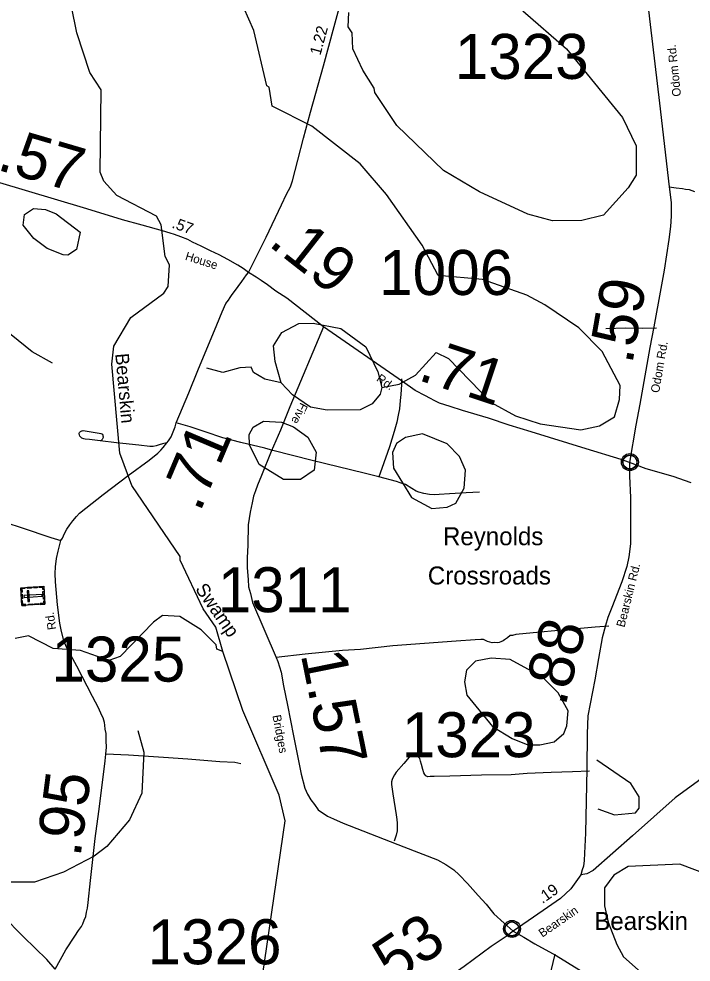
# Model space of a CAD drawing. Extents: x 2093524 to 2270757, y 289120 to 570408.
# Drawn here: x 2162986 to 2170455, y 474784 to 485262 of the extents above; entities that cross this region are included whole.
import ezdxf

# ---------------------------------------------------------------- set-up
doc = ezdxf.new("R2010")
doc.units = 0
for name, color, linetype in [('Exist Civil Demographics Community CELL', 7, 'Continuous'), ('Exist Civil Demographics Community Label', 7, 'Continuous'), ('Exist Cultural Cemetery CELL', 7, 'Continuous'), ('Exist Hydrographic Creek Single Shore', 7, 'Continuous'), ('Exist Hydrographic Misc Water Feature', 7, 'Continuous'), ('Exist Hydrographic Pond Under 1500 Sq Ft', 7, 'Continuous'), ('Exist Hydrographic Swamp Label', 7, 'Continuous'), ('Exist Road Non-System Type 51', 7, 'Continuous'), ('Exist Road Secondary Mileage Hundredths English Label', 7, 'Continuous'), ('Exist Road Secondary Type 51 Attributed', 7, 'Continuous'), ('Exist Road Secondary Type 51 Label', 7, 'Continuous'), ('Exist Road Secondary Type 51 Number Label', 7, 'Continuous')]:
    doc.layers.add(name, color=color, linetype=linetype)

msp = doc.modelspace()

# ---------------------------------------------------------------- linework, layer by layer
at = {"layer": 'Exist Civil Demographics Community CELL'}
for points in [[(2169697, 480351), (2169698, 480356), (2169700, 480363), (2169703, 480370), (2169706, 480376), (2169709, 480382), (2169713, 480387), (2169717, 480391), (2169722, 480396), (2169727, 480400), (2169733, 480404), (2169738, 480407), (2169743, 480409), (2169748, 480412), (2169754, 480413), (2169758, 480414), (2169763, 480415), (2169767, 480416), (2169773, 480416), (2169778, 480416), (2169783, 480416), (2169788, 480415), (2169793, 480414), (2169798, 480413), (2169803, 480411), (2169810, 480408), (2169816, 480404), (2169821, 480401), (2169827, 480397), (2169830, 480394), (2169834, 480389), (2169838, 480385), (2169841, 480380), (2169844, 480375), (2169847, 480370), (2169849, 480365), (2169850, 480360), (2169851, 480355), (2169852, 480349), (2169853, 480344), (2169853, 480338), (2169853, 480333), (2169853, 480327), (2169852, 480322), (2169850, 480315), (2169848, 480310), (2169846, 480304), (2169843, 480298), (2169839, 480293), (2169836, 480288), (2169832, 480284), (2169826, 480279), (2169821, 480275), (2169816, 480271), (2169812, 480269), (2169805, 480265), (2169798, 480263), (2169792, 480261), (2169786, 480260), (2169781, 480259), (2169777, 480259), (2169771, 480259), (2169767, 480260), (2169761, 480260), (2169755, 480262), (2169751, 480263), (2169745, 480265), (2169741, 480267), (2169737, 480269), (2169730, 480273), (2169725, 480277), (2169720, 480282), (2169715, 480287), (2169712, 480291), (2169709, 480295), (2169705, 480302), (2169703, 480306), (2169702, 480310), (2169699, 480318), (2169697, 480325), (2169697, 480330), (2169696, 480336), (2169696, 480341), (2169697, 480347)], [(2168387, 475165), (2168388, 475171), (2168390, 475177), (2168393, 475185), (2168396, 475190), (2168399, 475196), (2168403, 475201), (2168407, 475206), (2168411, 475210), (2168417, 475215), (2168422, 475218), (2168427, 475221), (2168432, 475224), (2168438, 475226), (2168443, 475228), (2168448, 475229), (2168452, 475230), (2168457, 475230), (2168463, 475231), (2168467, 475231), (2168473, 475230), (2168478, 475230), (2168483, 475229), (2168488, 475227), (2168493, 475225), (2168500, 475222), (2168506, 475219), (2168511, 475215), (2168516, 475211), (2168519, 475208), (2168524, 475204), (2168527, 475199), (2168531, 475195), (2168534, 475190), (2168536, 475184), (2168538, 475179), (2168540, 475174), (2168541, 475170), (2168542, 475164), (2168543, 475159), (2168543, 475153), (2168543, 475147), (2168542, 475142), (2168541, 475136), (2168540, 475130), (2168538, 475124), (2168535, 475119), (2168532, 475113), (2168529, 475108), (2168526, 475103), (2168521, 475098), (2168516, 475093), (2168511, 475089), (2168506, 475086), (2168502, 475083), (2168495, 475080), (2168488, 475077), (2168482, 475076), (2168475, 475074), (2168471, 475074), (2168466, 475074), (2168461, 475074), (2168456, 475074), (2168451, 475075), (2168445, 475076), (2168440, 475077), (2168435, 475079), (2168431, 475081), (2168427, 475084), (2168420, 475088), (2168414, 475092), (2168409, 475096), (2168405, 475101), (2168402, 475105), (2168399, 475109), (2168395, 475117), (2168393, 475120), (2168391, 475124), (2168389, 475132), (2168387, 475139), (2168386, 475144), (2168386, 475151), (2168386, 475156), (2168386, 475162)]]:
    msp.add_lwpolyline(points, close=True, dxfattribs=at)
for centre, radius in [((2169775, 480338), 94.3), ((2169775, 480339), 76.7), ((2168465, 475153), 94.3), ((2168464, 475153), 76.7)]:
    msp.add_circle(centre, radius, dxfattribs=at)
at = {"layer": 'Exist Cultural Cemetery CELL'}
for points in [[(2163020, 478744), (2163008, 478943), (2163263, 478959), (2163275, 478760)], [(2163052, 478946), (2163052, 478935), (2163020, 478933), (2163023, 478892), (2163012, 478891), (2163008, 478943)], [(2163016, 478818), (2163013, 478870), (2163024, 478871), (2163027, 478819)], [(2163043, 478855), (2163044, 478836), (2163247, 478849), (2163245, 478867)], [(2163086, 478789), (2163104, 478790), (2163097, 478908), (2163079, 478907)], [(2163125, 478939), (2163082, 478936), (2163081, 478948), (2163125, 478950)], [(2163191, 478943), (2163148, 478940), (2163147, 478952), (2163190, 478954)], [(2163265, 478925), (2163253, 478925), (2163252, 478947), (2163211, 478944), (2163211, 478955), (2163263, 478959)], [(2163260, 478816), (2163254, 478901), (2163266, 478902), (2163271, 478817)], [(2163064, 478747), (2163063, 478758), (2163031, 478756), (2163028, 478797), (2163017, 478796), (2163020, 478744)], [(2163138, 478752), (2163094, 478749), (2163094, 478760), (2163137, 478763)], [(2163205, 478756), (2163161, 478753), (2163161, 478764), (2163204, 478767)], [(2163272, 478793), (2163261, 478792), (2163262, 478770), (2163222, 478768), (2163223, 478757), (2163274, 478760)]]:
    msp.add_lwpolyline(points, close=True, dxfattribs=at)
at = {"layer": 'Exist Hydrographic Creek Single Shore'}
for points in [[(2165253, 478235), (2165176, 478503), (2165033, 478709), (2164780, 479249), (2164780, 479291), (2164243, 480079), (2164107, 480436), (2164018, 481426), (2164042, 481628), (2164231, 481946), (2164596, 482214), (2164646, 482289), (2164661, 482531), (2164610, 482621), (2164568, 482973), (2164516, 483072), (2164074, 483301), (2163931, 483458), (2163889, 483560), (2163900, 484475), (2163774, 484665), (2163630, 485107), (2163450, 486006)], [(2164014, 467432), (2164010, 468065), (2164247, 468999), (2164236, 469491), (2164251, 469658), (2164366, 470059), (2164381, 470367), (2164454, 470717), (2164552, 470951), (2165138, 471903), (2165149, 472616), (2165237, 472845), (2165619, 474121), (2165945, 476355), (2165878, 476638), (2165473, 477578), (2165253, 478235)]]:
    msp.add_lwpolyline(points, dxfattribs=at)
at = {"layer": 'Exist Hydrographic Misc Water Feature'}
for points in [[(2167019, 481169), (2167210, 481204), (2167393, 481305), (2167624, 481557), (2167758, 481488), (2168235, 481000), (2168502, 480853), (2168778, 480763), (2169229, 480698), (2169436, 480740), (2169603, 480841), (2169660, 481034), (2169668, 481191), (2169466, 481566), (2169206, 481830), (2168830, 482087), (2168629, 482193), (2168136, 482366), (2167645, 482412), (2167468, 482747), (2167072, 483310), (2166779, 483650), (2166243, 484071), (2165802, 484293), (2165766, 484503), (2165741, 484520), (2165596, 485133), (2165486, 485385)], [(2163360, 481439), (2163134, 481565), (2162741, 481878)], [(2165902, 481220), (2165718, 481260), (2165593, 481335), (2165568, 481394), (2165442, 481384), (2165252, 481335), (2165076, 481381)], [(2165253, 478235), (2165186, 478260), (2165177, 478309), (2165010, 478476), (2164775, 478625), (2164584, 478633), (2164483, 478562), (2164111, 478180), (2163986, 478136), (2163670, 478244), (2163369, 478267), (2163093, 478407), (2162944, 478380)], [(2164308, 477356), (2164376, 477115), (2164352, 476662), (2164214, 476364), (2163964, 476070), (2163824, 475961), (2163484, 475784), (2163159, 475673), (2162718, 475672), (2162159, 475811), (2161691, 475981), (2161097, 476328), (2160529, 476710), (2160136, 477006), (2159691, 477471), (2159422, 477903), (2159305, 478036), (2159029, 478183), (2158887, 478199)], [(2169419, 476485), (2169603, 476419), (2169836, 476444), (2169877, 476496), (2169877, 476621), (2169784, 476770), (2169408, 477027)]]:
    msp.add_lwpolyline(points, dxfattribs=at)
at = {"layer": 'Exist Hydrographic Pond Under 1500 Sq Ft'}
for points in [[(2168915, 483020), (2168640, 483094), (2168105, 483341), (2167705, 483579), (2167185, 484078), (2166941, 484444), (2166933, 484493), (2166808, 484693), (2166697, 484931), (2166689, 485108), (2166646, 485175), (2166654, 485332)], [(2168586, 485352), (2169071, 484929), (2169693, 484166), (2169844, 483851), (2169846, 483526), (2169755, 483384), (2169482, 483081), (2169240, 483023), (2168915, 483020)], [(2163478, 482640), (2163302, 482713), (2163152, 482821), (2163034, 482971), (2163050, 483088), (2163150, 483155), (2163283, 483146), (2163400, 483098), (2163668, 482892), (2163627, 482700), (2163529, 482639), (2163478, 482640)], [(2165902, 481220), (2165834, 481455), (2165816, 481629), (2165907, 481778), (2166098, 481879), (2166257, 481883), (2166565, 481824), (2166841, 481618), (2166975, 481343), (2167019, 481169)], [(2167019, 481169), (2167001, 481094), (2166911, 480984), (2166779, 480918), (2166412, 480915), (2166228, 480948), (2166027, 481087), (2165902, 481220)], [(2165925, 480147), (2165657, 480310), (2165547, 480529), (2165546, 480644), (2165588, 480728), (2165705, 480795), (2165904, 480781), (2166038, 480729), (2166196, 480614), (2166290, 480448), (2166266, 480249), (2166116, 480147), (2165925, 480147)], [(2167576, 479822), (2167743, 479839), (2167842, 479883), (2167933, 480048), (2167949, 480248), (2167881, 480400), (2167746, 480541), (2167471, 480654), (2167280, 480612), (2167180, 480545), (2167139, 480444), (2167149, 480270), (2167350, 479945), (2167576, 479822)], [(2168774, 477197), (2168932, 477230), (2169040, 477323), (2169073, 477408), (2169088, 477575), (2168979, 477774), (2168803, 477948), (2168444, 478145), (2168235, 478159), (2168061, 478127), (2167961, 478027), (2167937, 477899), (2167963, 477751), (2168248, 477401), (2168465, 477269), (2168641, 477196), (2168774, 477197)], [(2171041, 473993), (2171274, 474021), (2171523, 474154), (2171697, 474396), (2171713, 474524), (2171661, 474807), (2171543, 475062), (2171133, 475477), (2170798, 475694), (2170331, 475873), (2169756, 475846), (2169598, 475750), (2169491, 475608), (2169492, 475411), (2169535, 475227), (2169628, 474979), (2169703, 474843), (2170197, 474407), (2170507, 474217), (2171041, 473993)]]:
    msp.add_lwpolyline(points, dxfattribs=at)
at = {"layer": 'Exist Road Non-System Type 51'}
for points in [[(2170072, 481825), (2169920, 481823), (2169726, 481825), (2169508, 481818)], [(2167238, 481262), (2167236, 481200), (2167231, 481089), (2167224, 481021), (2167216, 480932), (2167202, 480859), (2167187, 480781), (2167157, 480679), (2167103, 480509), (2167020, 480267), (2166984, 480175)], [(2165807, 480468), (2165719, 480493), (2165451, 480556), (2165253, 480609), (2165056, 480674), (2164888, 480730), (2164734, 480773)], [(2163889, 480573), (2163829, 480581), (2163773, 480588), (2163723, 480594), (2163707, 480596), (2163697, 480600), (2163687, 480604), (2163675, 480614), (2163665, 480628), (2163659, 480640), (2163657, 480650), (2163657, 480660), (2163661, 480668), (2163663, 480672), (2163671, 480678), (2163685, 480684), (2163691, 480686), (2163701, 480688), (2163789, 480674), (2163879, 480661), (2163897, 480657), (2163909, 480651), (2163915, 480647), (2163921, 480639), (2163921, 480629), (2163923, 480621), (2163923, 480613), (2163921, 480605), (2163917, 480597), (2163911, 480589), (2163899, 480579), (2163889, 480573)], [(2164631, 480553), (2164583, 480541), (2164545, 480529), (2164513, 480518), (2164477, 480512), (2164441, 480512), (2164321, 480528), (2164070, 480552), (2163889, 480573)], [(2166984, 480175), (2166838, 480210), (2166670, 480251), (2166532, 480286), (2166244, 480358), (2165807, 480468)], [(2168105, 480005), (2167955, 479998), (2167771, 479987), (2167657, 479978), (2167605, 479974), (2167547, 479978), (2167487, 479991), (2167429, 480005), (2167401, 480017), (2167351, 480045), (2167283, 480088), (2167223, 480108), (2167181, 480122), (2166984, 480175)], [(2169539, 478515), (2169387, 478505), (2169021, 478471), (2168700, 478441), (2168506, 478422), (2168470, 478412), (2168444, 478411), (2168416, 478385), (2168382, 478365), (2168366, 478353), (2168342, 478343), (2168324, 478335), (2168304, 478331), (2168272, 478333), (2168246, 478330), (2168194, 478346), (2168172, 478356), (2168148, 478366), (2168120, 478367), (2168054, 478365), (2167844, 478350), (2167141, 478296), (2166783, 478258), (2166582, 478245), (2166166, 478205), (2165846, 478168)], [(2165453, 476987), (2165385, 477001), (2165219, 477008), (2164863, 477040), (2164593, 477058), (2164205, 477084), (2163953, 477093)], [(2169324, 476905), (2169138, 476898), (2168900, 476890), (2168635, 476879), (2168457, 476866), (2168125, 476862), (2167775, 476848), (2167601, 476845), (2167557, 476845), (2167529, 476843), (2167507, 476855), (2167495, 476868), (2167485, 476887), (2167473, 476922), (2167458, 476978), (2167450, 477018), (2167440, 477046), (2167420, 477068), (2167406, 477074), (2167384, 477078), (2167370, 477078), (2167360, 477076), (2167350, 477074), (2167324, 477061), (2167264, 476991), (2167179, 476895), (2167159, 476865), (2167143, 476839), (2167135, 476811), (2167127, 476787), (2167128, 476757), (2167142, 476655), (2167177, 476419), (2167186, 476367), (2167188, 476329), (2167188, 476293), (2167191, 476243), (2167179, 476193), (2167157, 476127)], [(2168770, 474107), (2168782, 474177), (2168842, 474439), (2168944, 474874)]]:
    msp.add_lwpolyline(points, dxfattribs=at)
at = {"layer": 'Exist Road Secondary Type 51 Attributed'}
for points in [[(2170155, 487199), (2170125, 487087), (2170063, 486833), (2170039, 486700), (2170014, 486577), (2169960, 486311), (2169944, 486213), (2169936, 486147), (2169932, 486074), (2169928, 486024), (2169927, 485905), (2169951, 485617), (2169999, 485199), (2170104, 484326), (2170212, 483395)], [(2165538, 482443), (2165732, 482838), (2165904, 483195), (2165961, 483314), (2166003, 483398), (2166026, 483464), (2166085, 483694), (2166147, 483936), (2166228, 484227), (2166371, 484741), (2166491, 485178), (2166555, 485420)], [(2165538, 482443), (2165480, 482489), (2165418, 482525), (2165307, 482590), (2165211, 482640), (2165115, 482685), (2165011, 482736), (2164917, 482780), (2164862, 482812), (2164786, 482839), (2164716, 482865), (2164666, 482882), (2164582, 482908), (2164356, 482971), (2164138, 483029), (2163743, 483153), (2162733, 483450)], [(2170212, 483395), (2170234, 483223), (2170234, 483069), (2170226, 482954), (2170208, 482812), (2170155, 482471), (2170119, 482266), (2170039, 481840), (2169995, 481612), (2169953, 481360), (2169884, 480982), (2169839, 480749), (2169770, 480334)], [(2170212, 483395), (2170287, 483384), (2170359, 483378), (2170394, 483370), (2170433, 483367), (2170491, 483344)], [(2163452, 479467), (2163470, 479493), (2163493, 479547), (2163521, 479593), (2163551, 479641), (2163586, 479687), (2163628, 479736), (2163660, 479770), (2163732, 479828), (2163923, 479977), (2164201, 480189), (2164434, 480360), (2164532, 480439), (2164564, 480471), (2164591, 480501), (2164631, 480553), (2164647, 480573), (2164679, 480619), (2164702, 480673), (2164724, 480730), (2164734, 480773), (2164876, 481108), (2164973, 481357), (2165184, 481864), (2165245, 482006), (2165286, 482100), (2165316, 482139), (2165334, 482166), (2165356, 482199), (2165383, 482233), (2165465, 482343), (2165514, 482419), (2165538, 482443)], [(2166369, 481840), (2165964, 482158), (2165841, 482237), (2165749, 482307), (2165679, 482356), (2165623, 482392), (2165538, 482443)], [(2166369, 481840), (2165995, 480952), (2165892, 480695), (2165789, 480457), (2165683, 480189), (2165639, 480084), (2165617, 480020), (2165593, 479959), (2165577, 479885), (2165556, 479784), (2165533, 479640), (2165529, 479414), (2165524, 479275), (2165524, 479165), (2165533, 479036), (2165538, 478952), (2165560, 478878), (2165583, 478780), (2165846, 478168), (2165862, 478125), (2165900, 478004), (2165928, 477853), (2165971, 477637), (2166037, 477298), (2166124, 476872), (2166163, 476717), (2166194, 476649), (2166229, 476585), (2166269, 476536), (2166311, 476477), (2166414, 476407), (2166483, 476374), (2166589, 476326), (2167262, 476064), (2167638, 475920), (2167730, 475870), (2167819, 475808), (2167878, 475755), (2167972, 475657), (2168090, 475523), (2168177, 475429), (2168263, 475321), (2168378, 475216), (2168479, 475127)], [(2169770, 480334), (2169676, 480368), (2169287, 480486), (2168679, 480676), (2168434, 480750), (2168202, 480826), (2167916, 480910), (2167777, 480956), (2167661, 480993), (2167607, 481020), (2167552, 481050), (2167503, 481074), (2167390, 481132), (2167250, 481234), (2166369, 481840)], [(2169770, 480334), (2169772, 480184), (2169782, 479947), (2169782, 479684), (2169782, 479534), (2169782, 479431), (2169761, 479287), (2169742, 479179), (2169684, 479007), (2169573, 478725), (2169528, 478613), (2169503, 478523), (2169467, 478388), (2169425, 478155), (2169385, 477921), (2169308, 477519), (2169299, 477321), (2169295, 476930), (2169283, 476218), (2169272, 475996), (2169265, 475914), (2169260, 475849), (2169243, 475809), (2169228, 475753)], [(2170457, 480110), (2170255, 480177), (2169955, 480265), (2169770, 480334)], [(2162843, 479668), (2163025, 479607), (2163342, 479500), (2163452, 479467)], [(2163388, 474704), (2163509, 474919), (2163608, 475071), (2163648, 475134), (2163682, 475178), (2163698, 475208), (2163711, 475250), (2163731, 475292), (2163739, 475338), (2163748, 475382), (2163756, 475446), (2163783, 475692), (2163834, 476156), (2163875, 476458), (2163903, 476692), (2163945, 477019), (2163953, 477093), (2163959, 477173), (2163958, 477242), (2163956, 477323), (2163947, 477373), (2163943, 477416), (2163937, 477444), (2163929, 477472), (2163923, 477498), (2163908, 477524), (2163870, 477608), (2163805, 477736), (2163629, 478070), (2163518, 478276), (2163486, 478353), (2163455, 478477), (2163443, 478549), (2163416, 478753), (2163392, 479007), (2163390, 479101), (2163393, 479175), (2163405, 479269), (2163422, 479349), (2163440, 479423), (2163452, 479467)], [(2173021, 479035), (2172897, 478802), (2172844, 478713), (2172772, 478598), (2172740, 478564), (2172663, 478486), (2172565, 478402), (2172412, 478275), (2172083, 478023), (2171250, 477372), (2170975, 477164), (2170739, 476977), (2170536, 476798), (2170277, 476608), (2169803, 476187), (2169367, 475802), (2169296, 475763), (2169228, 475753)], [(2169228, 475753), (2169120, 475597), (2169003, 475492), (2168810, 475356), (2168479, 475127)], [(2163388, 474704), (2163298, 474814), (2163039, 475064), (2162805, 475301)], [(2168479, 475127), (2168399, 475070), (2168234, 474959), (2167933, 474734), (2167606, 474504), (2167323, 474311), (2167104, 474164), (2167005, 474105), (2166927, 474046), (2166887, 474016), (2166852, 473986), (2166796, 473934), (2166736, 473867), (2166633, 473743), (2166506, 473562), (2166432, 473464), (2166391, 473422), (2166331, 473361)], [(2168479, 475127), (2168595, 475061), (2168719, 474988), (2168954, 474856), (2169461, 474547)]]:
    msp.add_lwpolyline(points, dxfattribs=at)

# ---------------------------------------------------------------- texts
at = {"layer": 'Exist Civil Demographics Community Label'}
for s, p in [('Reynolds', (2167698, 479415)), ('Crossroads', (2167530, 478979)), ('Bearskin', (2169379, 475141))]:
    msp.add_text(s, height=200, dxfattribs=at).set_placement(p)
at = {"layer": 'Exist Hydrographic Swamp Label'}
for s, rotation, p in [('Bearskin', 275.1409, (2164057, 481541)), ('Swamp', 304.7159, (2164940, 478928))]:
    msp.add_text(s, height=150, rotation=rotation, dxfattribs=at).set_placement(p)
at = {"layer": 'Exist Road Secondary Mileage Hundredths English Label'}
for s, height, rotation, p in [('1.22', 125, 74.6849, (2166336, 484850)), ('.57', 500, 343.632, (2162730, 483590)), ('.57', 125, 339.9773, (2164678, 482945)), ('.19', 500, 321.8634, (2165746, 482752)), ('.59', 500, 80.0636, (2169800, 481416)), ('.71', 500, 341.5651, (2167408, 481254)), ('.71', 500, 67.0311, (2164997, 479771)), ('.88', 500, 75.1474, (2169055, 477615)), ('1.57', 500, 281.5031, (2166117, 478202)), ('.95', 500, 82.6699, (2163670, 475942)), ('.19', 125, 35.1505, (2168803, 475428)), ('.53', 500, 33.885, (2166986, 474426))]:
    msp.add_text(s, height=height, rotation=rotation, dxfattribs=at).set_placement(p)
at = {"layer": 'Exist Road Secondary Type 51 Label'}
for s, rotation, p in [('Odom Rd.', 95.9201, (2170343, 484404)), ('House', 342.6001, (2164827, 482587)), ('Odom Rd.', 80.1689, (2170098, 481102)), ('Rd.', 324.0349, (2166951, 481248)), ('Five', 243.2309, (2166117, 481006)), ('Bearskin Rd.', 75.872, (2169714, 478497)), ('Rd.', 98.4737, (2163402, 478482)), ('Bridges', 280.604, (2165803, 477522)), ('Bearskin', 34.6458, (2168802, 475055))]:
    msp.add_text(s, height=95, rotation=rotation, dxfattribs=at).set_placement(p)
at = {"layer": 'Exist Road Secondary Type 51 Number Label'}
for s, p in [('1323', (2167829, 484595)), ('1006', (2166990, 482195)), ('1311', (2165196, 478671)), ('1325', (2163348, 477900)), ('1323', (2167240, 477060)), ('1326', (2164417, 474760))]:
    msp.add_text(s, height=500, dxfattribs=at).set_placement(p)

doc.saveas('drawing.dxf')
